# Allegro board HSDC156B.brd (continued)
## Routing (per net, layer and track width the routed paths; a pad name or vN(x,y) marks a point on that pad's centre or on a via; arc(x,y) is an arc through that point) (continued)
N16769693: length 7.6
  TOP w0.203: U1.35 30.85,41.67 31.43,42.24 31.43,43.13
  TOP w0.229: 31.43,43.13 31.43,43.92 33.51,46.01 R3.1 R4.1
N16786555: length 2.3
  TOP w0.229: R13.2 JMP4.1
N16786563: length 2.3
  TOP w0.229: R15.1 35.62,50.36
  TOP w0.254: 35.62,50.36 JMP4.3
N16786728: length 2.3
  TOP w0.229: R14.2 JMP3.1
N16786746: length 2.3
  TOP w0.229: R17.1 19.11,50.36
  TOP w0.254: 19.11,50.36 JMP3.3
N16786904: length 2.3
  TOP w0.229: R12.2 JMP2.1
N16786924: length 2.3
  TOP w0.229: R18.1 26.73,50.36
  TOP w0.254: 26.73,50.36 JMP2.3
N16791721: length 4
  TOP w0.203: U6.21 41.91,27.3 43.82,29.22
  TOP w0.229: R60.1 44.05,29.52 43.82,29.29 43.82,29.22
N16791724: length 3.4
  TOP w0.203: U6.22 41.51,27.59 42.27,28.35
  TOP w0.229: R61.1 43.16,29.25 42.27,28.35
N16791727: length 3.1
  TOP w0.203: 41.94,28.65 41.11,27.82 U6.23
  TOP w0.229: R62.1 41.94,28.65
N16791992: length 4.4
  TOP w0.203: 39.01,28.03 39.51,27.54 U6.27
  TOP w0.229: R58.2 R63.1 39.01,29.08 39.01,28.03
N16792053: length 4.4
  TOP w0.203: 38.87,27.42 39.11,27.19 U6.28
  TOP w0.229: R57.2 R59.1 38.24,28.06 38.87,27.42
N16792062: length 5.7
  TOP w0.203: 37.98,26.21 38.16,26.03 U6.29
  TOP w0.229: R56.2 36.1,29.93 36.4,29.62 36.4,29.14 37.98,27.57 37.98,26.21
N16792248: length 5.1
  TOP w0.203: 36.62,27.4 36.87,27.14 36.87,26.04 37.67,25.23 U6.31
  TOP w0.229: 36.62,27.4 36.6,27.4 R55.1
N16792431: length 3.4
  TOP w0.203: 36.36,24.5 36.83,24.03 U6.34
  TOP w0.229: 36.36,24.5 35.86,25 R52.2
N16792503: length 2.6
  TOP w0.203: C12.1 36.12,23.63 U6.35
N16792701: length 3.2
  TOP w0.203: 37.28,21.31 37.6,21.63 U6.40
  TOP w0.229: 37.28,21.31 37.27,21.3 35.39,21.3 R51.1
N16792704: length 3.5
  TOP w0.203: 37.4,20.81 37.82,21.23 U6.41
  TOP w0.229: R50.1 35.33,20.19 36.78,20.19 37.4,20.81
N16792707: length 3.8
  TOP w0.203: 37.52,20.28 38.08,20.83 U6.42
  TOP w0.229: 37.52,20.28 36.17,18.92 R49.1
N16792812: length 2.9
  TOP w0.203: U6.43 39.11,19.47 38.86,19.23
  TOP w0.229: 38.86,19.23 38.21,18.57 R46.1
N16792872: length 19.1
  TOP w0.203: 39.51,19.15 U6.44
  TOP w0.229: SW1.1 SW1.2 46.19,14.76 45.58,15.37 40.81,15.37 40.21,15.97 40.21,17.25 39.86,17.6 R45.1 39.51,19.15
N16793299: length 2.6
  TOP w0.203: 40.93,19.08 41.11,19.26 U6.48
  TOP w0.229: R44.1 40.93,19.08
N16793302: length 2.8
  TOP w0.203: 41.71,18.06 41.51,18.26 U6.49
  TOP w0.229: 41.71,18.06 R42.1
N16793739: length 2.6
  TOP w0.203: 43.51,19.43 U6.54
  TOP w0.229: R69.2 43.55,17.77 43.55,19.38 43.51,19.43
N16793744: length 2.8
  TOP w0.203: 44.07,19.5 43.91,19.67 U6.55
  TOP w0.229: R43.2 44.07,18.16 44.07,19.5
N16794056: length 1.8
  TOP w0.229: R68.2 40.49,11.52 U10.7
N16794233: length 2.4
  TOP w0.203: 41.75,3.71 R67.1
  TOP w0.229: U10.3 41.75,3.71
N16796118: length 4
  TOP w0.229: R72.2 46.61,64.84 R73.1 46.59,66.1 U12.5
N16796449: length 2.1
  TOP w0.508: R75.1 D5.1
N16804565: length 2.6
  TOP w0.229: JMP9.1 R22.2
N16876297: length 5.9
  TOP w0.203: C3.2 23.22,35.76 arc(23.37,35.65) 23.55,35.62 25.03,35.62 arc(25.21,35.65) 25.37,35.76 26.43,36.81 arc(26.73,37.02) 27.09,37.09 27.92,37.09 27.97,37.14 U1.11
N16876304: length 5.8
  TOP w0.203: U1.12 28.1,36.74 28.07,36.72 27.09,36.72 arc(26.87,36.68) 26.69,36.55 25.63,35.5 arc(25.36,35.31) 25.03,35.25 23.55,35.25 arc(23.37,35.21) 23.22,35.11 C4.2
N16876335: length 3.8
  TOP w0.203: U1.17 29.65,35.17 29.63,35.16 29.63,35.04 arc(29.59,34.73) 29.48,34.44 29.45,34.39 arc(29.35,34.16) 29.32,33.9 29.32,32.37 arc(29.38,32.09) C2.2
N16876344: length 3.8
  TOP w0.203: U1.16 29.25,35.17 29.26,35.15 29.26,35.04 arc(29.24,34.82) 29.16,34.62 29.13,34.57 arc(29,34.25) 28.95,33.9 28.95,32.37 arc(28.9,32.1) C1.2
N16883926: length 2.1
  TOP w0.229: R21.2 JMP6.1
N16883933: length 2.1
  TOP w0.229: R20.2 JMP7.1
N16883940: length 2.2
  TOP w0.229: R19.2 JMP8.1
N16885672: length 5.8
  TOP w0.203: U1.38 29.65,42.61
  TOP w0.229: R2.2 R1.2 29.65,45.33 29.65,42.61
N16894778: length 2.3
  TOP w0.229: R11.2 JMP5.1
N16894795: length 2.3
  TOP w0.229: R16.1 44.51,50.36
  TOP w0.254: 44.51,50.36 JMP5.3
N16919722: length 5.8
  TOP w0.203: U1.13 27.98,36.35 27.15,35.51
  TOP w0.229: R31.2 26.17,32.44 26.7,32.97 26.7,35.07 27.15,35.51
N16919741: length 4.7
  TOP w0.203: 27.45,35.22 28.17,35.95 U1.14
  TOP w0.229: R32.2 27.45,35.22
N16919748: length 8.6
  TOP w0.203: 27.59,41.34 27.78,41.14 U1.1
  TOP w0.229: 27.59,41.34 26.74,42.18 24.28,42.18 22.88,43.58 R30.2

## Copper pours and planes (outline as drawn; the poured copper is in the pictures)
3.3V on TOP: 33.65,64.16 33.65,57.47 33.7,57.42 36.63,57.42 36.71,57.49 36.71,61.7 35.96,62.45 35.96,64.22 35.86,64.33 33.81,64.33
3.3V on BOTTOM: 33.89,57.61 33.89,59.27 34.04,59.42 36.28,59.42 36.38,59.31 36.38,57.67 36.27,57.56 33.95,57.56
3.3V on L3_PWR: 42.48,59.75 42.48,75.2 42.81,75.54 56.41,75.54 56.52,75.42 56.52,19.21 56.27,18.96 45.7,18.96 45.47,19.19 45.47,22.44 45.7,22.66 45.93,22.66 45.93,22.66 46.43,22.66 46.8,22.3 46.8,20.86 47.3,20.35 52.71,20.35 53.22,20.85 53.22,31.92 52.58,32.55 33.12,32.55 32.49,31.92 32.49,22.18 32.27,21.96 18.39,21.96 16.15,24.19 16.15,54.22 15.43,54.94 9.43,54.94 8.7,55.67 8.7,58.76 9.25,59.31 26.55,59.31 27.05,58.81 29.82,58.81 30.33,59.31 38.05,59.31 38.51,58.85 41.58,58.85 ; 7 cut-outs
5V on TOP: 44.71,24.79 44.71,25.27 44.71,25.3 44.73,25.32 45.79,25.32 46.5,26.02 50.83,26.02 50.98,25.87 50.98,23.53 50.84,23.39 46.89,23.39 46.59,23.7 46.59,24.49 46.34,24.73
5V on TOP: 45.13,62.23 45.13,57.34 45.2,57.26 47.51,57.26 47.63,57.39 47.63,62.17 47.53,62.27 45.17,62.27
5V on BOTTOM: 46.32,25.16 46.97,24.5 48.64,24.5 48.98,24.17 50.87,24.17 51.01,24.31 51.01,26.95 56.41,32.35 56.41,55.78 53.16,59.03 45.31,59.03 44.68,58.39 44.68,55.82 50.77,49.73 50.77,35.07 46.32,30.61 ; 1 cut-out
5V on L4_SIG: 40.3,28.71 40.42,28.58 40.42,27.46 42.47,25.41 45.46,25.41 45.89,25.85 46.57,25.85 46.57,25.89 46.73,26.05 50.84,26.05 51.32,25.57 51.32,18.09 50.49,17.25 39.54,17.25 38.51,18.28 38.51,23.18 37.27,24.42 37.27,26.36 39.62,28.71 ; 2 cut-outs
GND on TOP: 21.04,66.57 21.38,66.23 21.38,65.61 22.39,65.61 22.39,69.9 22.18,70.1 6.48,70.1 6.25,69.88 6.25,67.08 6.53,66.8 9.67,66.8 10.57,65.91 10.57,63.54 10.89,63.22 12.55,63.22 13.05,63.72 13.05,66.08 13.54,66.57
GND on TOP: 42.47,65 42.47,67.79 42.96,68.28 46.45,68.28 46.61,68.44 46.61,74.1 46.41,74.3 37.78,74.3 37.56,74.08 37.56,63.2 37.67,63.08 38.65,63.08 38.65,68.16 38.69,68.2 41.33,68.2 41.85,67.68 41.85,65
GND on TOP: 38.96,26.18 38.96,20.68 42.36,20.68 42.36,26.18
GND on TOP: 44.42,58.99 42.97,58.99 42.88,59.08 42.88,59.96 42.94,60.02 44.42,60.02 44.47,59.97 44.47,59.04
GND on TOP: 18.32,58.59 18.24,58.67 18.24,59.3 18.3,59.36 20.04,59.36 20.08,59.32 20.08,58.61 20.06,58.59
GND on TOP: 29.99,67.69 29.99,59.84 30.14,59.69 33.32,59.69 33.34,59.72 33.34,61.77 33.11,62 31.63,62 30.94,62.69 30.94,67.64 31.39,68.08 34.93,68.08 35.22,68.38 35.22,74.09 35.04,74.27 25.9,74.27 25.78,74.16 25.78,68.35 26.03,68.11 29.57,68.11
GND on BOTTOM: 42.16,20.78 39.11,20.78 39.03,20.85 39.03,25.92 39.21,26.1 42.09,26.1 42.27,25.92 42.27,20.89
GND on BOTTOM: 0.64,29.42 2.4,29.42 2.4,24.22 2.61,24.01 4.8,24.01 4.8,20.29 4.74,20.23 2.63,20.23 2.4,20 2.4,15.68 3.26,14.83 4.13,14.83 4.62,14.34 4.62,12.75 4.26,12.4 0.84,12.4 0.64,12.6 0.64,14.86
GND on BOTTOM: 31.35,61.91 31.35,60.2 31.21,60.05 30.2,60.05 30.09,60.16 30.09,61.86 30.19,61.96 31.3,61.96
GND on L2_GND: 0.64,1.25 0.64,75.17 1,75.54 55.98,75.54 56.52,74.99 56.52,1.25 55.91,0.64 1.25,0.64 ; 61 cut-outs
GND on L5_GND: 0.64,1.25 0.64,75.17 1.03,75.56 55.95,75.56 56.52,74.99 56.52,1.25 55.91,0.64 1.25,0.64 ; 17 cut-outs
VBUS_C on TOP: 46.57,21.51 45.57,21.51 45.52,21.56 44.71,21.56 44.71,22.07 46.5,22.07 46.79,22.36 51.37,22.36 51.5,22.49 51.5,26.22 51.13,26.59 46.66,26.59 45.61,25.54 44.71,25.54 44.71,26.14 45.32,26.14 45.39,26.21 45.39,30.54 45.54,30.69 55.35,30.69 55.69,30.35 55.69,19.46 55.4,19.18 47.43,19.18 46.97,19.63 46.97,21.11
VBUS_C on L4_SIG: 46.73,41.6 47.26,42.13 56.17,42.13 56.51,41.79 56.51,26.97 56.42,26.88 46.87,26.88 46.73,27.02
VBUS_IN on BOTTOM: 3.49,18.06 5.2,18.06 7.44,15.83 10.98,15.83 11.09,15.73 11.09,9.38 10.9,9.19 9.48,9.19 9.2,9.47 9.2,11.23 3.42,17.02 3.42,18
LDO_3V3 on L3_PWR: 56.52,18.42 56.52,1.51 55.65,0.64 33.36,0.64 33.14,0.86 33.14,31.81 33.4,32.07 52.42,32.07 52.72,31.77 52.72,21.07 52.35,20.7 47.42,20.7 47.1,21.02 47.1,22.4 46.77,22.73 46.77,23.16 46.54,23.4 45.74,23.4 45.19,22.85 45.19,18.94 45.56,18.57 56.38,18.57 ; 2 cut-outs
PAD1 on TOP (solid shape): 45.14,27.66 45.14,26.6 45.09,26.55 44.55,26.55 44.45,26.44 44.45,25.79 44.35,25.69 43.96,25.69 43.88,25.77 43.88,26.1 43.95,26.16 44.12,26.16 44.24,26.28 44.24,26.29 44.3,26.35 44.3,27.15 44.86,27.71 44.86,27.71 45.09,27.71
PAD1 on BOTTOM: 42.75,26.07 42.84,26.16 44.35,26.16 44.42,26.1 44.42,23.72 44.35,23.66 42.82,23.66 42.75,23.72
PAD2 on TOP (solid shape): 44.45,21.12 44.45,20.39 44.47,20.36 45.09,20.36 45.14,20.31 45.14,19.25 45.09,19.2 44.83,19.2 44.28,19.75 44.28,20.59 44.12,20.74 43.95,20.74 43.88,20.81 43.88,21.14 43.96,21.22 44.35,21.22
PAD2 on BOTTOM: 42.83,23.28 44.38,23.28 44.43,23.23 44.43,20.93 44.25,20.75 42.91,20.75 42.74,20.92 42.74,23.19
SYS_5V on TOP: 39.04,59.66 39.04,67.14 39.18,67.28 41.14,67.28 41.23,67.2 41.23,64.68 41.37,64.54 42.73,64.54 42.75,64.52 42.75,63.09 42.73,63.07 41.34,63.07 41.23,62.95 41.23,59.69 41.16,59.63 39.08,59.63
SYS_5V on TOP: 18.17,20.02 16.54,20.02 16.45,19.93 15.38,19.93 15.29,20.02 15.29,20.3 15.4,20.4 16.5,20.4 16.59,20.31 18.16,20.31 18.19,20.29 18.19,20.04
SYS_5V on TOP: 29.57,67.26 29.4,67.42 27.41,67.42 26.97,66.98 26.97,64.5 25.15,62.69 25.15,58.82 25.33,58.65 29.32,58.65 29.57,58.89
SYS_5V on TOP: 29.32,20.02 27.69,20.02 27.6,19.93 26.53,19.93 26.48,19.98 26.48,19.98 26.48,20.31 26.57,20.4 27.65,20.4 27.74,20.31 29.31,20.31 29.34,20.29 29.34,20.04
SYS_5V on BOTTOM: 28.81,19.92 26.47,19.92 26.41,19.98 26.41,20.37 26.48,20.44 28.82,20.44 28.83,20.43 28.83,19.94
SYS_5V on BOTTOM: 15.47,19.92 15.3,19.92 15.24,19.98 15.24,20.37 15.31,20.44 17.89,20.44 17.9,20.42 17.9,19.93 17.89,19.92 17.64,19.92
SYS_5V on BOTTOM: 17.6,14.84 17.6,10.78 17.37,10.55 14.12,10.55 13.87,10.8 13.87,15.73 13.99,15.85 16.59,15.85
SYS_5V on BOTTOM: 27.69,62.26 29.35,62.26 29.49,62.12 29.49,59.88 29.39,59.77 27.75,59.77 27.63,59.89 27.63,62.2
SYS_5V on BOTTOM: 39.27,62.29 40.92,62.29 41.07,62.14 41.07,59.91 40.96,59.8 39.32,59.8 39.21,59.91 39.21,62.23
SYS_5V on L3_PWR: 0.68,2.26 0.68,75.33 0.81,75.46 41.68,75.46 41.87,75.27 41.87,60.26 41.33,59.72 39.17,59.72 38.71,60.19 30.09,60.19 29.46,59.56 27.56,59.56 26.94,60.19 17.04,60.19 8.78,60.24 7.93,59.39 7.93,55.78 9.37,54.33 15.03,54.33 15.43,53.94 15.43,24.33 17.92,21.84 32.1,21.84 32.44,21.5 32.44,2.47 30.99,1.02 1.93,1.02 ; 2 cut-outs
N16791273 on TOP: 44.71,20.73 45.27,20.73 45.53,20.47 45.53,18.72 47.68,16.57 55.68,16.57 55.85,16.74 55.85,18.67 55.71,18.81 47.15,18.81 46.59,19.37 46.59,21.06 46.34,21.31 46.1,21.34 44.71,21.34
N16795663 on TOP: 33.44,67.31 33.32,67.44 31.63,67.44 31.45,67.26 31.45,62.78 31.53,62.7 33.2,62.7 33.24,62.74 33.24,64.3 33.44,64.5
N16795996 on TOP: 43.13,67.21 43.13,60.91 43.32,60.72 44.53,60.72 44.57,60.76 44.57,62.78 44.87,63.08 46.3,63.08 46.31,63.09 46.31,63.6 46.3,63.61 45.5,63.61 44.47,64.64 44.01,64.64 43.76,64.9 43.76,67.2 43.72,67.23 43.16,67.23
N16796371 on TOP: 7.36,62.6 9.4,62.6 10.13,61.87 13.05,61.87 14.7,63.52 22.17,63.52 22.36,63.33 22.36,58.67 22.32,58.64 20.72,58.64 20.61,58.75 20.61,59.92 20.39,60.14 18.94,60.14 18.35,60.74 7.26,60.74 7.24,60.76 7.24,62.48

Small or netless copper shapes (teardrops, artwork), in the pictures only: 4 on TOP

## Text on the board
BOTTOM: LAYER 6 - BOTTOM SIDE
Ref Des/Assembly Bottom: ASSEMBLY BOTTOM
Board Geometry/Soldermask Bottom: SOLDERMASK BOTTOM
Package Geometry/Pastemask Bottom: PASTEMASK BOTTOM
Ref Des/Silkscreen Bottom: HSDC156B | SILKSCREEN BOTTOM
TOP: LAYER 1 - TOP SIDE
Ref Des/Assembly Top: ASSEMBLY TOP
Board Geometry/Soldermask Top: SOLDERMASK TOP
Package Geometry/Pastemask Top: PASTEMASK TOP
Ref Des/Silkscreen Top: INTERFACE ADAPTER | HSDC156B | A | GND | 3.3V | B | PP_HV2 | CONF2_SDA | C | HPDIN | INPUT | 2.5A MAX | CONF0 | CONF1_SCL | SILKSCREEN TOP
L2_GND: LAYER 2 - GROUND
L3_PWR: LAYER 3 - POWER
L4_SIG: LAYER 4 - SIGNAL
L5_GND: LAYER 5 - GROUND
XSECTION_CHART: *  DIELECTRIC - MEGTRON6 R-5670 4.9MIL (2116*1) 4.8 MIL | *  SURFACE - AIR 0 MIL | *  DIELECTRIC - TAIYO PSR 4000 HFX DI-GREEN 1 MIL | L1 TOP CONDUCTOR - COPPER_1/2OZ_PLATED 1.4 MIL | L2 L2_GND PLANE - COPPER_1.0OZ 1.26 MIL | *  DIELECTRIC - MEGTRON6 R-5775 4MIL 1/1 (1035*2) 3.937 MIL | L3 L3_PWR PLANE - COPPER_1.0OZ 1.26 MIL | *  DIELECTRIC - MEGTRON6 R-5775 24.6 MIL 1/1 (2116*5) 24.6 MIL | *  DIELECTRIC - MEGTRON6 R-5670 4.9MIL (2116*1) 4.3 MIL | L4 L4_SIG CONDUCTOR - COPPER_1.0OZ 1.26 MIL | L5 L5_GND PLANE - COPPER_1.0OZ 1.26 MIL | L6 BOTTOM CONDUCTOR - COPPER_1/2OZ_PLATED 1.4 MIL | *  DIELECTRIC - MEGTRON6 R-5670 4.9MIL (2116*1) 4.6 MIL | DESIGN CROSS SECTION CHART | ___________________________ | TOTAL THICKNESS 60.814 MIL | 1-6
DIMENSION: FABRICATION DRAWING | CAD ORIGIN
User.6: LAYER 1 | LAYER 2 | LAYER 3 | LAYER 4 | LAYER 5 | LAYER 6 | LAYER | NO. | TABLE 1: | TOP | L2_GND | L3_PWR | NAME | L4_SIG | L5_GND | L6_ BOTTOM | 90  +/- 10% | 100  +/- 10% | NA | DIFFIRENTIAL PAIR | IMPEDANCE (OHMS) | 0.0080" | 0.0060" | DIFF TRACE | WIDTH | SPACING | 0.0065" | 50 +/- 10% | SINGLE ENDED | 0.0090" | TRACE WIDTH | LAYER 2 AND 5 | REFERENCE | SPECIAL FAB NOTES: | PLACE DRILL CHART HERE: | MIN. ANNULAR RING 2 MIL EXTERNAL PER IPC-6012C | REGISTRATION TOLERANCES: METAL +/- X MIL,HOLES +/- X MIL | IMPEDANCE CONTROL: | BOARD SIZE (REFER ALSO ARRAY/PANEL PROFILING INFORMATION) | MIXED DIELECTRIC: | LAMINATE MATERIAL: | THICKNESS: | TOLERANCE: | COPPER THICKNESS (FINISHED): | BOARD FINISH: | NUMBER OF LAYERS: | MIN. TRACK WIDTH: | MIN. CLEARANCE  : | MIN. VIA PAD/DRILL: | THIEVING ALLOWED: | THROUGH-HOLE VIA TREATMENT: | X | OUTER: | INNER SIGNAL: | INNER PLANE: | OTHER: | SILKSCREEN: | SOLDERMASK: (PER IPC-6011,6012) | BOARD SURFACE TREATMENT: | ADDITIONAL REQUIREMENTS: | VENDOR MARKING: | SILKSCREEN COLOR: | SOLDERMASK COLOR: | VIA FILL USING COPPER AND PLATED OVER SMOOTH | VIA FILL USING NON-CONDUCTIVE EPOXY AND PLATED OVER SMOOTH | FOR WIRE BONDING: | VENDOR DATE CODE,UL,LOGO: | FR-4 HIGH Tg | 0.062" +/-10% | IPC-6012C CLASS 2 | IPC-6012C CLASS 3 | MICRO-SECTION | CERTIFICATES OF COMPLIANCE | NICKEL/GOLD (ENIG) | IMMERSION TIN | HARD GOLD | IN AN OPEN AREA | 1/4 OZ. | OPEN | NO | 6 | 6.0 MIL | 4 MIL | 14.0/6.0 MIL | NONE | DESIGN INFORMATION | ROGERS 4350B | 0.093" +/-10% | YES | TDR REPORTS/COUPONS | WHITE | GREEN | SOFT GOLD | TENTED | 1/2 OZ. | BOTTOM | BOW & TWIST: | ORGANIC (OSP) | OTHER | WHERE INDICATED (SEE DRAWING) | YES - SEE TABLE 1 | ETCH | IDENTIFIER: | BLUE | RoHS | 1.0 OZ. | SILKSCREEN | PER SUPPLIED ARTWORK | ALL  VIAS | Megtron 6 | ELECTRICAL TEST | UL 94V-0 | HASL | 2.0 OZ. | BREAK-AWAY | ENEPIG
User.13: FIGURE | FINISHED_SIZE | 49.0x28.0 | 67.0x24.0 | 75.0x24.0 | 79.0x28.0 | 87.0x24.0 | 118.0x40.0 | 138.0x40.0 | 34.0x20.0 | SLOT HOLES: TOP to BOTTOM | ALL UNITS ARE IN MILS | TOLERANCE_DRILL | +4.0/-4.0 | PLATED | NON-PLATED | QTY | 2 | 1 | 14 | TOTAL HOLES:
User.14: FIGURE | FINISHED_SIZE | 6.0 | 8.0 | 10.0 | 12.0 | 39.37 | 40.0 | 24.0 | 33.46 | 55.0 | 67.0 | 125.0 | DRILL CHART: TOP to BOTTOM | ALL UNITS ARE IN MILS | TOLERANCE_DRILL | +3.0/-3.0 | +3.94/-1.97 | +3.94/-3.94 | +0.98/-0.98 | +4.0/-4.0 | +2.0/-2.0 | PLATED | NON-PLATED | QTY | 17 | 7 | 215 | 216 | 10 | 27 | 4 | 16 | 1 | 2 | 524 | TOTAL HOLES:
